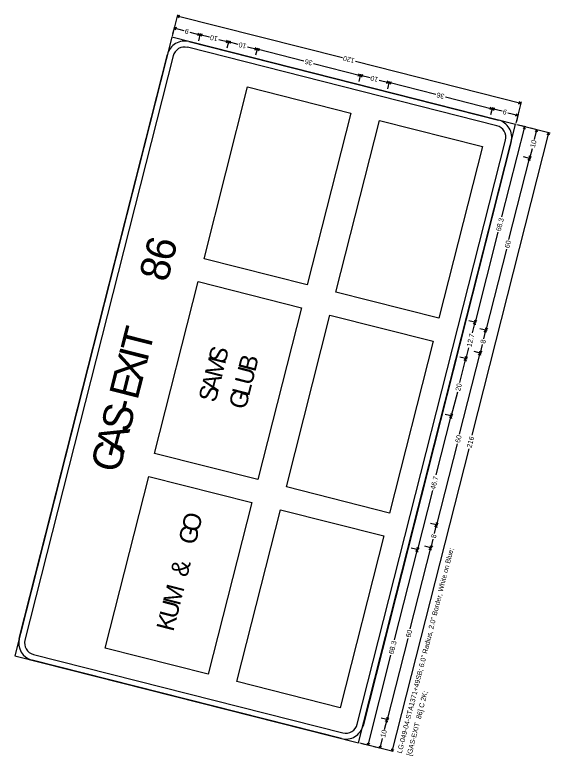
# Model space of a CAD drawing. Extents: x 670257 to 671518, y 737783 to 738188.
# Drawn here: x 670748.8 to 670775.22, y 738002.85 to 738039.45 of the extents above; entities that cross this region are included whole.
import ezdxf

# ---------------------------------------------------------------- set-up
doc = ezdxf.new("R2010")
doc.units = 0
doc.layers.add('R_SIGN', color=7, linetype='Continuous')

msp = doc.modelspace()

# ---------------------------------------------------------------- linework, layer by layer
at = {"layer": 'R_SIGN'}
for p, q in [((670756.829, 738039.447), (670756.564, 738038.4)), ((670756.935, 738039.413), (670756.814, 738039.387)), ((670764.974, 738037.317), (670756.814, 738039.387)), ((670756.908, 738039.306), (670756.814, 738039.387)), ((670756.678, 738038.848), (670756.587, 738038.489)), ((670756.783, 738038.815), (670756.662, 738038.788)), ((670757.157, 738038.663), (670756.662, 738038.788)), ((670756.756, 738038.708), (670756.662, 738038.788)), ((670757.44, 738038.591), (670757.935, 738038.466)), ((670757.814, 738038.439), (670757.935, 738038.466)), ((670757.841, 738038.546), (670757.935, 738038.466)), ((670757.95, 738038.526), (670757.859, 738038.167)), ((670758.055, 738038.492), (670757.935, 738038.466)), ((670758.416, 738038.344), (670757.935, 738038.466)), ((670758.028, 738038.385), (670757.935, 738038.466)), ((670758.867, 738038.229), (670759.348, 738038.107)), ((670759.228, 738038.081), (670759.348, 738038.107)), ((670759.255, 738038.188), (670759.348, 738038.107)), ((670759.363, 738038.167), (670759.272, 738037.808)), ((670759.469, 738038.134), (670759.348, 738038.107)), ((670759.829, 738037.985), (670759.348, 738038.107)), ((670759.442, 738038.027), (670759.348, 738038.107)), ((670760.281, 738037.871), (670760.762, 738037.749)), ((670760.641, 738037.722), (670760.762, 738037.749)), ((670760.668, 738037.829), (670760.762, 738037.749)), ((670760.777, 738037.808), (670760.686, 738037.45)), ((670760.882, 738037.775), (670760.762, 738037.749)), ((670763.068, 738037.164), (670760.762, 738037.749)), ((670760.855, 738037.668), (670760.762, 738037.749)), ((670763.545, 738037.043), (670765.851, 738036.458)), ((670765.617, 738037.154), (670773.777, 738035.084)), ((670765.757, 738036.539), (670765.851, 738036.458)), ((670765.73, 738036.432), (670765.851, 738036.458)), ((670765.866, 738036.518), (670765.775, 738036.159)), ((670765.971, 738036.484), (670765.851, 738036.458)), ((670766.332, 738036.336), (670765.851, 738036.458)), ((670765.944, 738036.377), (670765.851, 738036.458)), ((670766.783, 738036.221), (670767.264, 738036.1)), ((670767.171, 738036.18), (670767.264, 738036.1)), ((670767.279, 738036.159), (670767.188, 738035.8)), ((670758.138, 738027.405), (670760.29, 738035.886)), ((670760.29, 738035.886), (670765.378, 738034.596)), ((670767.144, 738036.073), (670767.264, 738036.1)), ((670767.385, 738036.126), (670767.264, 738036.1)), ((670769.57, 738035.515), (670767.264, 738036.1)), ((670767.358, 738036.019), (670767.264, 738036.1)), ((670770.047, 738035.394), (670772.353, 738034.809)), ((670773.792, 738035.144), (670773.527, 738034.097)), ((670773.657, 738035.058), (670773.777, 738035.084)), ((670773.684, 738035.165), (670773.777, 738035.084)), ((670772.233, 738034.783), (670772.353, 738034.809)), ((670772.26, 738034.89), (670772.353, 738034.809)), ((670772.368, 738034.869), (670772.277, 738034.51)), ((670772.368, 738034.869), (670772.277, 738034.51)), ((670772.474, 738034.835), (670772.353, 738034.809)), ((670772.847, 738034.684), (670772.353, 738034.809)), ((670772.447, 738034.728), (670772.353, 738034.809)), ((670765.378, 738034.596), (670763.227, 738026.114)), ((670773.131, 738034.612), (670773.625, 738034.486)), ((670773.505, 738034.46), (670773.625, 738034.486)), ((670773.532, 738034.567), (670773.625, 738034.486)), ((670773.641, 738034.546), (670773.55, 738034.187)), ((670764.641, 738025.756), (670766.792, 738034.237)), ((670766.792, 738034.237), (670771.881, 738032.947)), ((670775.217, 738033.605), (670773.571, 738034.022)), ((670774.02, 738033.909), (670773.661, 738034)), ((670771.37, 738018.69), (670775.157, 738033.62)), ((670772.833, 738029.479), (670773.96, 738033.924)), ((670773.88, 738033.83), (670773.96, 738033.924)), ((670773.987, 738033.803), (670773.96, 738033.924)), ((670774.618, 738033.757), (670774.259, 738033.848)), ((670774.437, 738033.291), (670774.558, 738033.772)), ((670774.478, 738033.679), (670774.558, 738033.772)), ((670774.585, 738033.651), (670774.558, 738033.772)), ((670775.076, 738033.527), (670775.157, 738033.62)), ((670775.183, 738033.5), (670775.157, 738033.62)), ((670771.881, 738032.947), (670769.73, 738024.465)), ((670774.322, 738032.839), (670774.2, 738032.358)), ((670773.185, 738028.355), (670774.2, 738032.358)), ((670774.26, 738032.343), (670773.901, 738032.434)), ((670774.26, 738032.343), (670773.901, 738032.434)), ((670774.119, 738032.265), (670774.2, 738032.358)), ((670774.174, 738032.479), (670774.2, 738032.358)), ((670774.281, 738032.452), (670774.2, 738032.358)), ((670774.226, 738032.238), (670774.2, 738032.358)), ((670772.639, 738028.714), (670771.512, 738024.269)), ((670773.064, 738027.88), (670772.049, 738023.877)), ((670763.227, 738026.114), (670758.138, 738027.405)), ((670755.701, 738017.793), (670757.852, 738026.274)), ((670757.852, 738026.274), (670762.94, 738024.983)), ((670769.73, 738024.465), (670764.641, 738025.756)), ((670762.94, 738024.983), (670760.789, 738016.502)), ((670762.203, 738016.143), (670764.354, 738024.625)), ((670764.354, 738024.625), (670769.443, 738023.334)), ((670771.571, 738024.254), (670771.212, 738024.345)), ((670771.571, 738024.254), (670771.212, 738024.345)), ((670771.378, 738023.741), (670771.512, 738024.269)), ((670771.431, 738024.176), (670771.512, 738024.269)), ((670771.485, 738024.39), (670771.512, 738024.269)), ((670771.592, 738024.362), (670771.512, 738024.269)), ((670771.538, 738024.148), (670771.512, 738024.269)), ((670772.109, 738023.862), (670771.75, 738023.953)), ((670771.942, 738023.454), (670772.049, 738023.877)), ((670771.968, 738023.784), (670772.049, 738023.877)), ((670772.023, 738023.998), (670772.049, 738023.877)), ((670772.13, 738023.97), (670772.049, 738023.877)), ((670772.075, 738023.756), (670772.049, 738023.877)), ((670769.443, 738023.334), (670767.292, 738014.853)), ((670771.19, 738023.001), (670771.056, 738022.474)), ((670771.869, 738023.169), (670771.762, 738022.746)), ((670770.747, 738018.743), (670771.762, 738022.746)), ((670771.822, 738022.731), (670771.463, 738022.822)), ((670771.681, 738022.653), (670771.762, 738022.746)), ((670771.736, 738022.867), (670771.762, 738022.746)), ((670771.843, 738022.84), (670771.762, 738022.746)), ((670771.788, 738022.626), (670771.762, 738022.746)), ((670771.116, 738022.459), (670770.757, 738022.55)), ((670770.758, 738021.299), (670771.056, 738022.474)), ((670770.976, 738022.38), (670771.056, 738022.474)), ((670771.03, 738022.594), (670771.056, 738022.474)), ((670771.137, 738022.567), (670771.056, 738022.474)), ((670771.083, 738022.353), (670771.056, 738022.474)), ((670770.637, 738020.821), (670770.339, 738019.647)), ((670770.399, 738019.631), (670770.04, 738019.722)), ((670770.313, 738019.767), (670770.339, 738019.647)), ((670770.42, 738019.74), (670770.339, 738019.647)), ((670769.6, 738016.732), (670770.339, 738019.647)), ((670770.259, 738019.553), (670770.339, 738019.647)), ((670770.366, 738019.526), (670770.339, 738019.647)), ((670770.626, 738018.268), (670769.611, 738014.265)), ((670771.199, 738018.017), (670767.413, 738003.087)), ((670760.789, 738016.502), (670755.701, 738017.793)), ((670753.263, 738008.18), (670755.414, 738016.662)), ((670755.414, 738016.662), (670760.503, 738015.371)), ((670767.292, 738014.853), (670762.203, 738016.143)), ((670769.404, 738015.96), (670768.665, 738013.045)), ((670760.503, 738015.371), (670758.351, 738006.89)), ((670759.765, 738006.531), (670761.916, 738015.013)), ((670761.916, 738015.013), (670767.005, 738013.722)), ((670769.671, 738014.249), (670769.312, 738014.34)), ((670769.504, 738013.842), (670769.611, 738014.265)), ((670769.53, 738014.171), (670769.611, 738014.265)), ((670769.585, 738014.385), (670769.611, 738014.265)), ((670769.692, 738014.358), (670769.611, 738014.265)), ((670769.637, 738014.144), (670769.611, 738014.265)), ((670767.005, 738013.722), (670764.854, 738005.24)), ((670769.431, 738013.557), (670769.324, 738013.134)), ((670768.309, 738009.131), (670769.324, 738013.134)), ((670768.725, 738013.03), (670768.366, 738013.121)), ((670768.639, 738013.166), (670768.665, 738013.045)), ((670768.746, 738013.139), (670768.665, 738013.045)), ((670769.384, 738013.119), (670769.025, 738013.21)), ((670769.244, 738013.04), (670769.324, 738013.134)), ((670769.298, 738013.254), (670769.324, 738013.134)), ((670769.405, 738013.227), (670769.324, 738013.134)), ((670769.351, 738013.013), (670769.324, 738013.134)), ((670767.538, 738008.6), (670768.665, 738013.045)), ((670768.584, 738012.952), (670768.665, 738013.045)), ((670768.691, 738012.925), (670768.665, 738013.045)), ((670768.188, 738008.655), (670767.173, 738004.652)), ((670758.351, 738006.89), (670753.263, 738008.18)), ((670767.344, 738007.835), (670766.216, 738003.39)), ((670764.854, 738005.24), (670759.765, 738006.531)), ((670767.233, 738004.637), (670766.874, 738004.728)), ((670767.147, 738004.773), (670767.173, 738004.652)), ((670767.254, 738004.746), (670767.173, 738004.652)), ((670767.051, 738004.171), (670767.173, 738004.652)), ((670767.092, 738004.559), (670767.173, 738004.652)), ((670767.199, 738004.532), (670767.173, 738004.652)), ((670766.936, 738003.72), (670766.815, 738003.239)), ((670767.473, 738003.072), (670765.827, 738003.489)), ((670766.276, 738003.375), (670765.917, 738003.466)), ((670766.19, 738003.511), (670766.216, 738003.39)), ((670766.297, 738003.484), (670766.216, 738003.39)), ((670766.874, 738003.224), (670766.515, 738003.315)), ((670766.788, 738003.359), (670766.815, 738003.239)), ((670766.895, 738003.332), (670766.815, 738003.239)), ((670767.386, 738003.208), (670767.413, 738003.087)), ((670767.493, 738003.18), (670767.413, 738003.087))]:
    msp.add_line(p, q, dxfattribs=at)
for points in [[(670765.768, 738003.504), (670773.512, 738034.038), (670756.549, 738038.34), (670748.805, 738007.806), (670765.768, 738003.504), (670765.768, 738003.504)], [(670757.397, 738038.125), (670772.663, 738034.253)], [(670772.592, 738033.97), (670757.325, 738037.842)], [(670749.02, 738008.655), (670756.334, 738037.492)], [(670756.616, 738037.42), (670749.303, 738008.583)], [(670765.7, 738004.424), (670773.014, 738033.261)], [(670773.296, 738033.189), (670765.983, 738004.352)], [(670749.725, 738007.874), (670764.991, 738004.002)], [(670764.919, 738003.719), (670749.653, 738007.591)]]:
    msp.add_lwpolyline(points, dxfattribs=at)
for centre, radius, start, end in [((670757.182, 738037.276), 0.875, 75.7686, 165.7688), ((670757.182, 738037.276), 0.583, 75.7686, 165.7688), ((670772.448, 738033.404), 0.583, 345.7686, 75.7688), ((670772.448, 738033.404), 0.875, 345.7686, 75.7688), ((670749.868, 738008.439), 0.875, 165.7688, 255.7684), ((670749.868, 738008.439), 0.583, 165.7688, 255.7684), ((670765.135, 738004.568), 0.875, 255.7684, 345.7686), ((670765.135, 738004.568), 0.583, 255.7684, 345.7686)]:
    msp.add_arc(centre, radius, start, end, dxfattribs=at)

# ---------------------------------------------------------------- texts
for s, height, rotation, p in [('9', 0.247, 165.7688, (670757.411, 738038.726)), ('10', 0.2469, 165.7688, (670758.838, 738038.364)), ('10', 0.2469, 165.7688, (670760.251, 738038.006)), ('36', 0.2469, 165.7688, (670763.515, 738037.178)), ('120', 0.2469, 165.7688, (670765.588, 738037.289)), ('10', 0.2469, 165.7688, (670766.754, 738036.356)), ('36', 0.2469, 165.7688, (670770.018, 738035.529)), ('9', 0.247, 165.7688, (670773.102, 738034.746)), ('10', 0.2469, 75.7686, (670774.457, 738032.869)), ('68.3', 0.2469, 75.7686, (670772.774, 738028.743)), ('6', 1.458, 75.7686, (670756.585, 738027.212)), ('60', 0.2469, 75.7686, (670773.199, 738027.909)), ('8', 1.458, 75.7686, (670756.33, 738026.209)), ('T', 1.458, 75.7686, (670755.431, 738022.66)), ('12.7', 0.2469, 75.7686, (670771.325, 738023.031)), ('8', 0.247, 75.7686, (670772.004, 738023.198)), ('S', 0.875, 75.7686, (670759.185, 738022.19)), ('X', 1.458, 75.7686, (670755.068, 738021.233)), ('I', 1.458, 75.7686, (670755.33, 738022.265)), ('B', 0.875, 75.7686, (670760.662, 738021.784)), ('M', 0.875, 75.7686, (670759.007, 738021.486)), ('U', 0.875, 75.7686, (670760.494, 738021.122)), ('E', 1.458, 75.7686, (670754.853, 738020.385)), ('A', 0.875, 75.7686, (670758.839, 738020.824)), ('L', 0.875, 75.7686, (670760.354, 738020.571)), ('20', 0.2469, 75.7686, (670770.772, 738020.851)), ('S', 0.875, 75.7686, (670758.699, 738020.273)), ('G', 0.875, 75.7686, (670760.191, 738019.926)), ('S', 1.458, 75.7686, (670754.445, 738018.773)), ('-', 1.458, 75.7686, (670754.678, 738019.692)), ('A', 1.458, 75.7686, (670754.183, 738017.741)), ('60', 0.2469, 75.7686, (670770.761, 738018.297)), ('216', 0.2469, 75.7686, (670771.334, 738018.046)), ('G', 1.458, 75.7686, (670753.939, 738016.78)), ('46.7', 0.2469, 75.7686, (670769.539, 738015.989)), ('O', 0.875, 75.7686, (670757.865, 738013.869)), ('G', 0.875, 75.7686, (670757.706, 738013.241)), ('8', 0.247, 75.7686, (670769.566, 738013.586)), ('LG-049-04-STA1371+49SB; 6.0" Radius, 2.0" Border, White on Blue; ', 0.24688, 75.7686, (670767.892, 738002.966)), ('&', 0.875, 75.7686, (670757.303, 738011.655)), ('M', 0.875, 75.7686, (670756.946, 738010.248)), ('U', 0.875, 75.7686, (670756.779, 738009.586)), ('K', 0.875, 75.7686, (670756.622, 738008.967)), ('60', 0.2469, 75.7686, (670768.323, 738008.685)), ('68.3', 0.2469, 75.7686, (670767.479, 738007.865)), ('[GAS-EXIT  86] C 2K; ', 0.24688, 75.7686, (670768.37, 738002.844)), ('10', 0.2469, 75.7686, (670767.071, 738003.749))]:
    msp.add_text(s, height=height, rotation=rotation, dxfattribs=at).set_placement(p)

doc.saveas('drawing.dxf')
